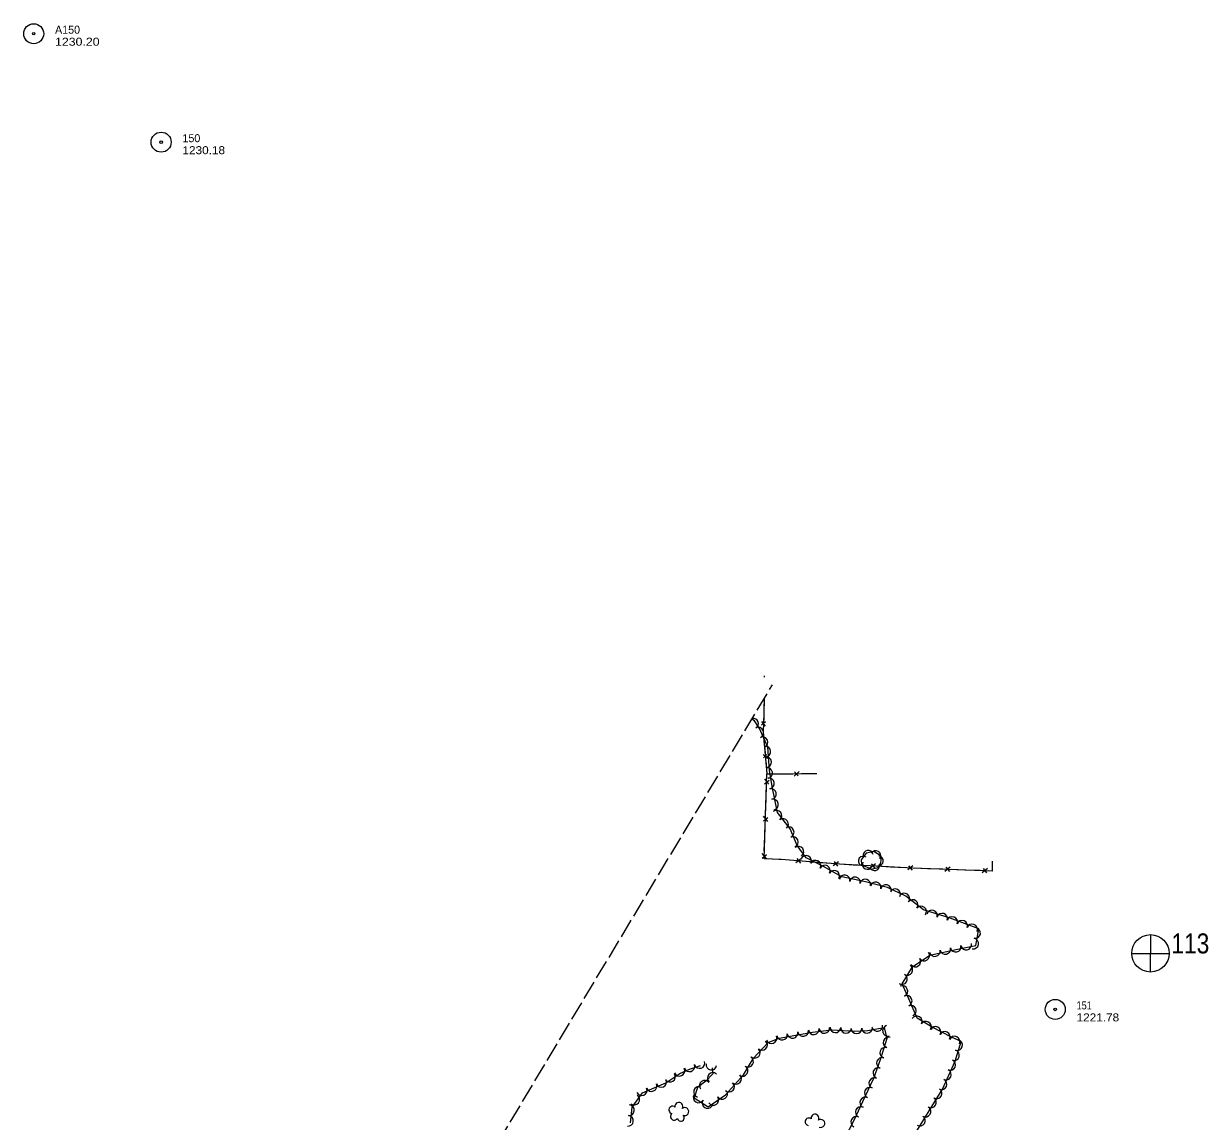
# Model space of a CAD drawing. Extents: x 298761 to 300931, y 48584 to 50968.
# Drawn here: x 299311 to 300199, y 50145 to 50968 of the extents above; entities that cross this region are included whole.
import ezdxf

# ---------------------------------------------------------------- set-up
doc = ezdxf.new("R2010")
doc.units = 0
doc.header["$LTSCALE"] = 2.4
doc.linetypes.add('LONG_DASHED', pattern=[7.5, 6, -1.5])
for name, color, linetype, lineweight in [('15', 7, 'Continuous', 13), ('18', 7, 'Continuous', 13), ('4', 7, 'Continuous', 13), ('6', 7, 'Continuous', 13)]:
    doc.layers.add(name, color=color, linetype=linetype, lineweight=lineweight)

msp = doc.modelspace()

# ---------------------------------------------------------------- linework, layer by layer
at = {"layer": '15'}
for p, q in [((299865.766, 50479.186), (299865.763, 50478.144)), ((299865.71, 50461.831), (299865.687, 50454.612)), ((299866.715, 50444.604), (299863.812, 50442.264)), ((299863.868, 50444.881), (299866.577, 50441.479)), ((299865.687, 50430.081), (299866.486, 50421.335)), ((299865.051, 50420.176), (299868.194, 50417.171)), ((299867.91, 50420.287), (299865.349, 50417.577)), ((299867.014, 50415.553), (299867.922, 50405.609)), ((299877.214, 50405.701), (299887.203, 50405.8)), ((299888.384, 50404.066), (299892.08, 50407.353)), ((299888.522, 50407.318), (299891.358, 50404.164)), ((299893.806, 50405.865), (299905.163, 50405.977)), ((299866.165, 50398.331), (299869.441, 50401.024)), ((299869.407, 50398.048), (299866.288, 50401.887)), ((299867.279, 50386.962), (299867.623, 50396.945)), ((299866.887, 50375.611), (299867.279, 50386.962)), ((299865.202, 50370.397), (299868.478, 50373.09)), ((299868.443, 50370.114), (299865.324, 50373.953)), ((299866.315, 50359.028), (299866.66, 50369.011)), ((299865.924, 50347.677), (299866.315, 50359.028)), ((299864.238, 50342.463), (299867.514, 50345.156)), ((299867.48, 50342.18), (299864.361, 50346.019)), ((299876.747, 50341.565), (299866.77, 50342.064)), ((299893.634, 50342.008), (299889.655, 50339.07)), ((299893.202, 50338.783), (299890.663, 50342.18)), ((299904.61, 50339.37), (299894.654, 50340.176)), ((299915.931, 50338.454), (299904.61, 50339.37)), ((299921.494, 50339.755), (299917.515, 50336.817)), ((299921.062, 50336.53), (299918.522, 50339.927)), ((299932.488, 50337.389), (299922.513, 50337.925)), ((299943.83, 50336.779), (299932.488, 50337.389)), ((299949.355, 50338.228), (299945.457, 50335.184)), ((299949.01, 50334.993), (299946.38, 50338.32)), ((299960.399, 50335.887), (299950.424, 50336.424)), ((299971.74, 50335.277), (299960.399, 50335.887)), ((299977.266, 50336.727), (299973.367, 50333.682)), ((299976.921, 50333.491), (299974.291, 50336.819)), ((299988.318, 50334.583), (299978.335, 50334.941)), ((299999.668, 50334.177), (299988.318, 50334.583)), ((300005.167, 50335.725), (300001.324, 50332.611)), ((300004.88, 50332.484), (300002.191, 50335.764)), ((300016.25, 50333.582), (300006.267, 50333.94)), ((300027.601, 50333.176), (300016.25, 50333.582)), ((300033.1, 50334.725), (300029.256, 50331.611)), ((300032.813, 50331.483), (300030.123, 50334.763))]:
    msp.add_line(p, q, dxfattribs=at)
for points in [[(299865.711, 50461.831), (299865.676, 50451.043), (299865.054, 50437.006), (299867.922, 50405.609)], [(299865.687, 50454.612), (299865.676, 50451.043), (299865.445, 50445.835)], [(299865.188, 50440.035), (299865.054, 50437.006), (299865.687, 50430.081)], [(300036.669, 50340.255), (300036.779, 50332.847), (299977.298, 50334.978), (299922.39, 50337.932), (299878.677, 50341.468), (299865.732, 50342.116), (299867.922, 50405.609), (299905.163, 50405.977)], [(299867.851, 50403.545), (299867.922, 50405.609), (299877.214, 50405.701)], [(299888.072, 50340.708), (299878.677, 50341.468), (299876.747, 50341.565)], [(300036.669, 50340.255), (300036.779, 50332.847), (300034.2, 50332.939)]]:
    msp.add_lwpolyline(points, dxfattribs=at)
at = {"layer": '18'}
for points in [[(299976.815, 50132.544), (299999.456, 50169.437), (300008.873, 50190.453), (300013.551, 50205.051), (300006.284, 50208.347), (299991.825, 50215.914), (299980.364, 50222.595), (299974.262, 50237.064), (299969.305, 50248.352), (299977.04, 50261.184), (299989.885, 50269.938), (300010.699, 50274.292), (300024.36, 50277.065), (300026.599, 50289.484), (300005.225, 50297.458), (299985.317, 50303.702), (299971.976, 50314.024), (299958.235, 50320.49), (299941.863, 50324.821), (299923.985, 50328.421), (299910.221, 50336.185), (299897.39, 50342.797), (299890.595, 50352.045), (299885.401, 50364.613), (299875.774, 50376.8), (299871.93, 50396.167), (299869.815, 50408.462), (299868.523, 50425.642), (299862.247, 50439.637), (299858.612, 50445.506), (299856.607, 50446.657)], [(299826.933, 50185.541), (299827.36, 50181.05), (299822.215, 50175.415), (299815.843, 50170.724), (299813.322, 50162.862), (299823.874, 50156.241), (299836.719, 50165.093), (299850.202, 50180.208), (299857.795, 50192.576), (299868.803, 50204.407), (299877.055, 50207.756), (299902.021, 50212.099), (299916.634, 50213.827), (299933.515, 50212.894), (299943.144, 50213.383), (299955.82, 50215.604), (299957.794, 50207.511), (299952.681, 50191.377), (299947.709, 50177.477), (299941.283, 50163.802), (299933.049, 50145.973), (299922.588, 50125.718)], [(299765.739, 50144.23), (299766.764, 50155.882), (299774.667, 50166.588), (299792.227, 50174.225), (299802.706, 50181.14), (299809.836, 50184.415), (299818.215, 50187.098)]]:
    msp.add_lwpolyline(points, dxfattribs=at)
msp.add_lwpolyline([(299953.544, 50344.046), (299948.106, 50347.391), (299942.241, 50346.387), (299938.53, 50341.357), (299938.79, 50337.865), (299946.093, 50334.226), (299951.18, 50335.599), (299953.158, 50338.68), (299953.437, 50341.162)], close=True, dxfattribs=at)
for centre, radius, start, end in [((299857.52, 50443.299), 3.995, 301.77991, 97.96105), ((299852.014, 50446.391), 3.995, 343.15342, 346.93198), ((299861.316, 50436.603), 3.995, 294.16131, 114.14599), ((299864.585, 50429.314), 3.995, 294.16131, 114.14599), ((299866.665, 50422.466), 3.995, 274.30842, 94.2931), ((299867.264, 50414.499), 3.995, 274.30842, 94.2931), ((299868.056, 50406.356), 3.995, 279.76822, 99.7529), ((299869.41, 50398.482), 3.995, 279.76822, 99.7529), ((299870.907, 50390.58), 3.995, 281.23394, 101.21861), ((299872.462, 50382.744), 3.995, 281.23394, 101.21861), ((299875.072, 50374.316), 3.995, 308.31428, 128.29896), ((299880.024, 50368.046), 3.995, 308.31428, 128.29896), ((299884.218, 50362.001), 3.995, 292.46159, 112.44627), ((299887.269, 50354.618), 3.995, 292.46159, 112.44627), ((299891.481, 50347.308), 3.995, 306.31437, 126.29905), ((299897.192, 50340.547), 3.995, 332.74496, 152.72963), ((299904.294, 50336.887), 3.995, 332.74496, 152.72963), ((299940.105, 50340.218), 3.714, 53.58874, 233.57342), ((299943.746, 50344.673), 3.714, 9.72168, 189.70636), ((299949.362, 50344.336), 3.714, 328.41133, 148.39601), ((299951.413, 50340.557), 3.714, 263.594, 83.57868), ((299911.283, 50333.185), 3.995, 330.58118, 150.56586), ((299918.241, 50329.26), 3.995, 330.58118, 150.56586), ((299943.154, 50337.862), 3.714, 153.52112, 333.5058), ((299948.651, 50336.93), 3.714, 195.11209, 15.09677), ((299926.096, 50325.863), 3.995, 348.62256, 168.60724), ((299933.928, 50324.286), 3.995, 348.62256, 168.60724), ((299941.634, 50322.719), 3.995, 345.19022, 165.1749), ((299949.357, 50320.676), 3.995, 345.19022, 165.1749), ((299957.081, 50318.632), 3.995, 345.19022, 165.1749), ((299963.994, 50315.469), 3.995, 334.80774, 154.79242), ((299970.816, 50312.278), 3.995, 322.27836, 142.26304), ((299977.135, 50307.389), 3.995, 322.27836, 142.26304), ((299983.454, 50302.5), 3.995, 322.27836, 142.26304), ((299991.61, 50299.537), 3.995, 342.59401, 162.57868), ((299999.233, 50297.146), 3.995, 342.59401, 162.57868), ((300006.71, 50294.672), 3.995, 339.54862, 159.5333), ((300014.196, 50291.88), 3.995, 339.54862, 159.5333), ((300021.681, 50289.087), 3.995, 339.54862, 159.5333), ((300023.917, 50286.391), 3.995, 259.78769, 79.77237), ((300017.202, 50277.746), 3.995, 191.48204, 11.46672), ((300022.499, 50278.528), 3.995, 259.78769, 79.77237), ((299985.706, 50269.62), 3.995, 214.28249, 34.26717), ((299993.722, 50272.877), 3.995, 191.82277, 11.80745), ((300001.542, 50274.513), 3.995, 191.82277, 11.80745), ((300009.362, 50276.148), 3.995, 191.82277, 11.80745), ((299973.15, 50258.781), 3.995, 238.92651, 58.91119), ((299979.104, 50265.121), 3.995, 214.28249, 34.26717), ((299969.026, 50251.939), 3.995, 238.92651, 58.91119), ((299969.426, 50242.877), 3.995, 293.71581, 113.70049), ((299972.616, 50235.586), 3.995, 292.87424, 112.85891), ((299975.721, 50228.225), 3.995, 292.87424, 112.85891), ((299950.544, 50216.802), 3.995, 189.94575, 9.93043), ((299958.562, 50213.186), 3.995, 103.71528, 283.69995), ((299980.173, 50220.286), 3.995, 329.76832, 149.753), ((299987.075, 50216.263), 3.995, 329.76832, 149.753), ((299994.143, 50212.341), 3.995, 332.38272, 152.36739), ((299871.257, 50207.659), 3.995, 202.09699, 22.08167), ((299879.239, 50210.258), 3.995, 189.87589, 9.86057), ((299887.11, 50211.627), 3.995, 189.87589, 9.86057), ((299894.981, 50212.997), 3.995, 189.87589, 9.86057), ((299902.974, 50214.317), 3.995, 186.75162, 6.7363), ((299910.908, 50215.255), 3.995, 186.75162, 6.7363), ((299919.216, 50215.778), 3.995, 176.84419, 356.82886), ((299927.193, 50215.338), 3.995, 176.84419, 356.82886), ((299934.949, 50215.061), 3.995, 182.91488, 2.89956), ((299942.928, 50215.466), 3.995, 182.91488, 2.89956), ((299958.984, 50204.345), 3.995, 72.42382, 252.40849), ((300001.221, 50208.637), 3.995, 332.38272, 152.36739), ((300008.489, 50205.051), 3.995, 335.61065, 155.59533), ((299858.77, 50196.693), 3.995, 227.07141, 47.05609), ((299864.212, 50202.542), 3.995, 227.07141, 47.05609), ((299956.571, 50196.729), 3.995, 72.42382, 252.40849), ((300008.091, 50194.863), 3.995, 252.23935, 72.22403), ((300010.529, 50202.471), 3.995, 252.23935, 72.22403), ((299817.396, 50189.031), 3.995, 197.763, 17.74768), ((299853.758, 50189.996), 3.995, 238.46094, 58.44562), ((299954.073, 50189.061), 3.995, 70.32564, 250.31032), ((300005.318, 50187.632), 3.995, 245.87112, 65.8558), ((299795.283, 50178.747), 3.995, 213.42813, 33.41281), ((299802.265, 50183.238), 3.995, 204.67825, 24.66292), ((299809.787, 50186.595), 3.995, 197.763, 17.74768), ((299826.26, 50187.785), 3.995, 169.88163, 349.8663), ((299827.272, 50177.853), 3.995, 47.61022, 227.5949), ((299849.578, 50183.188), 3.995, 238.46094, 58.44562), ((299951.382, 50181.538), 3.995, 70.32564, 250.31032), ((300002.051, 50180.341), 3.995, 245.87112, 65.8558), ((299781.363, 50171.78), 3.995, 203.51231, 23.49699), ((299788.689, 50174.967), 3.995, 203.51231, 23.49699), ((299821.216, 50172.083), 3.995, 36.36777, 216.35245), ((299839.478, 50171.327), 3.995, 228.27381, 48.25849), ((299844.796, 50177.289), 3.995, 228.27381, 48.25849), ((299948.356, 50173.938), 3.995, 64.83843, 244.82311), ((299998.784, 50173.051), 3.995, 245.87112, 65.8558), ((299768.372, 50161.581), 3.995, 233.57351, 53.55818), ((299774.037, 50168.594), 3.995, 203.51231, 23.49699), ((299816.626, 50163.257), 3.995, 147.90087, 327.88555), ((299816.962, 50167.366), 3.995, 72.22889, 252.21356), ((299827.719, 50161.43), 3.995, 214.57993, 34.56461), ((299834.297, 50165.963), 3.995, 214.57993, 34.56461), ((299941.589, 50159.478), 3.995, 65.21866, 245.20334), ((299944.958, 50166.707), 3.995, 64.83843, 244.82311), ((299990.897, 50159.489), 3.995, 238.47049, 58.45516), ((299995.076, 50166.298), 3.995, 238.47049, 58.45516), ((299764.466, 50153.625), 3.995, 264.98042, 84.9651), ((299797.221, 50153.911), 2.777, 50.98984, 258.76284), ((299801.904, 50156.547), 2.974, 328.01895, 189.25284), ((299806.289, 50152.669), 2.975, 245.66977, 128.64304), ((299823.394, 50159.011), 3.995, 147.90087, 327.88555), ((299938.24, 50152.225), 3.995, 65.21866, 245.20334), ((299986.719, 50152.679), 3.995, 238.47049, 58.45516), ((299763.766, 50145.667), 3.995, 264.98042, 84.9651), ((299798.381, 50148.985), 2.783, 127.66686, 328.6779), ((299803.327, 50148.008), 2.611, 190.375, 48.30761), ((299899.23, 50145.045), 2.777, 50.98984, 258.76284), ((299903.913, 50147.681), 2.974, 328.01895, 189.25284), ((299908.298, 50143.803), 2.975, 245.66977, 128.64304), ((299934.844, 50144.892), 3.995, 62.69289, 242.67757), ((299982.54, 50145.87), 3.995, 238.47049, 58.45516)]:
    msp.add_arc(centre, radius, start, end, dxfattribs=at)
at = {"layer": '4', "linetype": 'LONG_DASHED'}
msp.add_line((299332.839, 49573.576), (299872.076, 50472.442), dxfattribs=at)
at = {"layer": '4'}
for p, q in [((300155.285, 50285.229), (300155.22, 50257.375)), ((300141.376, 50271.199), (300169.281, 50271.186))]:
    msp.add_line(p, q, dxfattribs=at)
msp.add_circle((300155.337, 50271.207), 14, dxfattribs=at)
at = {"layer": '6'}
for centre, radius in [((299318.349, 50960.239), 7.5), ((299318.349, 50960.239), 0.96), ((299413.842, 50878.97), 7.5), ((299413.842, 50878.97), 0.96), ((300083.958, 50229.202), 7.5), ((300083.958, 50229.202), 0.96)]:
    msp.add_circle(centre, radius, dxfattribs=at)

# ---------------------------------------------------------------- texts
at = {"layer": '4', "width": 0.85}
msp.add_text('113', height=15, dxfattribs=at).set_placement((300170.989, 50271.137))
at = {"layer": '6'}
for s, p in [('A150', (299334.349, 50960.239)), ('150', (299429.842, 50878.97))]:
    msp.add_text(s, height=6, dxfattribs=at).set_placement(p)
for s, width, p in [('1230.20', 1.15, (299334.349, 50951.239)), ('1230.18', 1.1, (299429.842, 50869.97)), ('151', 0.85, (300099.958, 50229.202)), ('1221.78', 1.1, (300099.958, 50220.202))]:
    msp.add_text(s, height=6, dxfattribs=dict(at, width=width)).set_placement(p)

doc.saveas('drawing.dxf')
